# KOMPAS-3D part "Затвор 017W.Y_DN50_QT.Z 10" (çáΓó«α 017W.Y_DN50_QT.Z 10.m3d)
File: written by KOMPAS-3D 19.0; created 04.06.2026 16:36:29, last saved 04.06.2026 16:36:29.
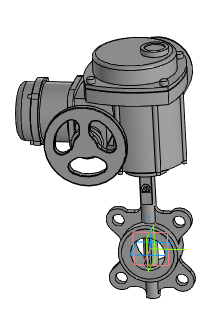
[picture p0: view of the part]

Document properties: Автор: Энергия; Полное имя файла: ..\..\..\3d для проектировщиков\017W разные\x.x Тип 017W.Y(S) Затвор дисковый поворотный межфланцевый\Затвор 017W.Y(S)_DN32-DN450_QT.Z\Затвор 017W.Y_DN50_QT.Z 10.a3d

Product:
- Part/product: Затвор 017W.Y_DN50_QT.Z 10
    Масса: 30.1978

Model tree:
1. Операция без истории:1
